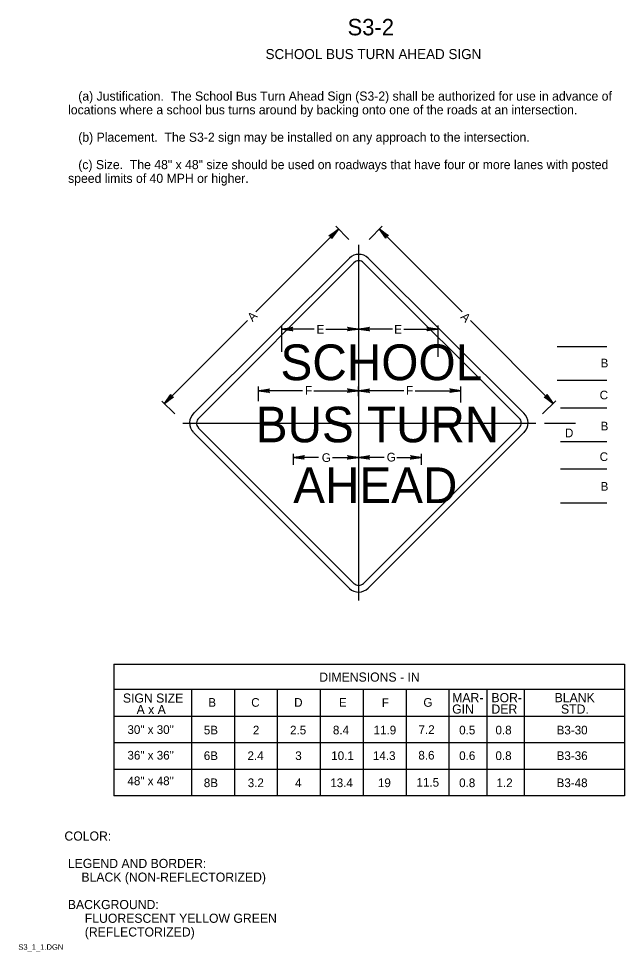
# Model space of a CAD drawing. Extents: x 0.013 to 0.178, y 0.004 to 0.259.
import ezdxf

# ---------------------------------------------------------------- set-up
doc = ezdxf.new("R2010")
doc.units = 0
for name, color, linetype in [('1', 7, 'Continuous'), ('2', 7, 'Continuous'), ('3', 7, 'Continuous')]:
    doc.layers.add(name, color=color, linetype=linetype)

# ---------------------------------------------------------------- blocks, each defined once
blk = doc.blocks.new('RARROW')
at = {"layer": '3'}
for p, q in [((-2.156, 0.28500000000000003), (-2.2665, 0.384625)), ((-2.2665, 0.384625), (0, 0)), ((0, 0), (-2.2665, -0.379125)), ((-2.156, 0.28500000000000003), (-2.075625, 0.12075)), ((0, 0), (-2.156, 0.28500000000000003)), ((-2.14975, -0.2705), (0, 0)), ((-2.075625, 0.12075), (0, 0)), ((0, 0), (-2.074, -0.108)), ((-2.2665, -0.379125), (-2.14975, -0.2705)), ((-2.074, -0.108), (-2.14975, -0.2705))]:
    blk.add_line(p, q, dxfattribs=at)

msp = doc.modelspace()

# ---------------------------------------------------------------- linework, layer by layer
at = {"layer": '1'}
for p, q in [((0.173625, 0.169375), (0.16, 0.169375)), ((0.173625, 0.160125), (0.16, 0.160125)), ((0.173625, 0.152625), (0.160875, 0.152625)), ((0.134125, 0.148375), (0.0575, 0.148375)), ((0.105625, 0.148375), (0.105625, 0.148375)), ((0.105625, 0.148375), (0.105625, 0.148375)), ((0.154125, 0.148375), (0.134125, 0.148375)), ((0.165, 0.148375), (0.1565, 0.148375)), ((0.173625, 0.143375), (0.160875, 0.143375)), ((0.173625, 0.135875), (0.160875, 0.135875)), ((0.173625, 0.12662500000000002), (0.160875, 0.12662500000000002))]:
    msp.add_line(p, q, dxfattribs=at)
at = {"layer": '3'}
for p, q in [((0.10300000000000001, 0.19875), (0.099375, 0.202375)), ((0.1085, 0.19875), (0.112125, 0.202375)), ((0.0775, 0.179), (0.100125, 0.201625)), ((0.134, 0.179), (0.111375, 0.201625)), ((0.105625, 0.19725), (0.105625, 0.1)), ((0.0605, 0.15125), (0.10312500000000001, 0.193625)), ((0.061875, 0.149875), (0.104375, 0.192375)), ((0.107, 0.192375), (0.149625, 0.149875)), ((0.10825, 0.193625), (0.150875, 0.15125)), ((0.07525, 0.176625), (0.0525, 0.153875)), ((0.13625, 0.176625), (0.15887500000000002, 0.153875)), ((0.084625, 0.168), (0.084625, 0.17525000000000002)), ((0.0935, 0.17425000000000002), (0.084625, 0.17425000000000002)), ((0.096625, 0.17425000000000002), (0.105625, 0.17425000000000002)), ((0.105625, 0.17550000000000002), (0.105625, 0.17525000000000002)), ((0.114875, 0.17425000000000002), (0.105625, 0.17425000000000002)), ((0.11800000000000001, 0.17425000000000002), (0.12737500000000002, 0.17425000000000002)), ((0.12737500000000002, 0.166625), (0.12737500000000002, 0.17525000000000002)), ((0.07825, 0.1545), (0.07825, 0.1585)), ((0.105625, 0.155875), (0.105625, 0.1585)), ((0.133625, 0.154125), (0.133625, 0.1585)), ((0.09025, 0.15737500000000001), (0.07825, 0.15737500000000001)), ((0.093375, 0.15737500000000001), (0.105625, 0.15737500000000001)), ((0.11800000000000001, 0.15737500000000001), (0.105625, 0.15737500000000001)), ((0.121125, 0.15737500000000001), (0.133625, 0.15737500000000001)), ((0.055375, 0.151), (0.051750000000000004, 0.1545)), ((0.156, 0.151), (0.15962500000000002, 0.154625)), ((0.10312500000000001, 0.10325000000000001), (0.0605, 0.145875)), ((0.104375, 0.104625), (0.06175, 0.14725)), ((0.149625, 0.14725), (0.107, 0.104625)), ((0.151, 0.146), (0.10825, 0.10337500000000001)), ((0.08778122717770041, 0.137125), (0.08778122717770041, 0.140125)), ((0.09469813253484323, 0.139125), (0.08778122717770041, 0.139125)), ((0.09845575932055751, 0.139125), (0.105625, 0.139125)), ((0.105625, 0.14025), (0.105625, 0.140125)), ((0.1126007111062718, 0.139125), (0.105625, 0.139125)), ((0.11608309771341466, 0.139125), (0.12286836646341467, 0.139125)), ((0.12286836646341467, 0.137125), (0.12286836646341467, 0.140125)), ((0.038625, 0.0825), (0.178375, 0.0825)), ((0.038625, 0.0825), (0.038625, 0.0465)), ((0.178375, 0.0825), (0.178375, 0.0465)), ((0.178375, 0.075625), (0.038625, 0.075625)), ((0.059875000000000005, 0.07575), (0.059875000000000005, 0.0465)), ((0.07162500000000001, 0.075625), (0.07162500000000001, 0.0465)), ((0.083375, 0.075625), (0.083375, 0.0465)), ((0.095125, 0.075625), (0.095125, 0.0465)), ((0.106875, 0.075625), (0.106875, 0.0465)), ((0.11862500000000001, 0.075625), (0.11862500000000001, 0.0465)), ((0.130375, 0.075625), (0.130375, 0.0465)), ((0.130375, 0.075625), (0.130375, 0.0465)), ((0.14075000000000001, 0.075625), (0.14075000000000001, 0.0465)), ((0.151, 0.075625), (0.151, 0.0465)), ((0.178375, 0.06825), (0.038625, 0.06825)), ((0.178375, 0.061), (0.038625, 0.061)), ((0.178375, 0.05375), (0.038625, 0.05375)), ((0.178375, 0.0465), (0.038625, 0.0465))]:
    msp.add_line(p, q, dxfattribs=at)
for centre, radius, start, end in [((0.10568750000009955, 0.19105909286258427), 0.003626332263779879, 45.03806666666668, 134.96193611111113), ((0.10569511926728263, 0.19107560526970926), 0.0018664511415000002, 45.03657222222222, 134.96044166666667), ((0.06311040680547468, 0.14857567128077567), 0.003732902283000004, 133.40603611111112, 225), ((0.14828904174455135, 0.14857109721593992), 0.0037233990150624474, 315.50790555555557, 46.011380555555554), ((0.06310643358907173, 0.148524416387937), 0.001827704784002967, 132.35789722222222, 223.9518611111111), ((0.14833975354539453, 0.14857807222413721), 0.0018258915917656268, 314.7557194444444, 45.25919444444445), ((0.1056239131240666, 0.10591956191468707), 0.003656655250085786, 226.8910611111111, 315.9033), ((0.1056874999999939, 0.10596032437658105), 0.0018723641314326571, 225.4938805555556, 314.5061194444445)]:
    msp.add_arc(centre, radius, start, end, dxfattribs=at)

# ---------------------------------------------------------------- block references
at = {"layer": '3', "xscale": 0.0013236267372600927}
for p, yscale, rotation in [((0.1, 0.2015), 0.0013093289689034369, 45.093773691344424), ((0.111375, 0.201625), 0.0013093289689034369, 134.9062263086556), ((0.084625, 0.17425000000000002), 0.001309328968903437, 180), ((0.105625, 0.17425000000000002), 0.001309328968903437, 180), ((0.0525, 0.153875), 0.0013093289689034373, -134.90622630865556), ((0.07825, 0.15737500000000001), 0.001309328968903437, 180), ((0.105625, 0.15737500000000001), 0.001309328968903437, 180), ((0.15887500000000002, 0.153875), 0.0013093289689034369, -45.093773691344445), ((0.08778122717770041, 0.139125), 0.001309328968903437, 180), ((0.105625, 0.139125), 0.001309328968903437, 180)]:
    msp.add_blockref('RARROW', p, dxfattribs=dict(at, yscale=yscale, rotation=rotation))
at = {"layer": '3', "xscale": 0.0013236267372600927, "yscale": 0.001309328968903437}
for p in [(0.105625, 0.17425000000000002), (0.12737500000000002, 0.17425000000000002), (0.105625, 0.15737500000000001), (0.133625, 0.15737500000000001), (0.105625, 0.139125), (0.12286836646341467, 0.139125)]:
    msp.add_blockref('RARROW', p, dxfattribs=at)

# ---------------------------------------------------------------- texts
at = {"layer": '1'}
for s, height, p in [('S3-2', 0.0045000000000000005, (0.10261806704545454, 0.254625)), ('SCHOOL BUS TURN AHEAD SIGN', 0.00275025, (0.08016680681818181, 0.248125)), ('COLOR:', 0.0024997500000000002, (0.025125, 0.034249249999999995)), (' LEGEND AND BORDER:', 0.0024997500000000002, (0.025125, 0.02674975)), ('     BLACK (NON-REFLECTORIZED)', 0.0024997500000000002, (0.025125, 0.023)), (' BACKGROUND:', 0.0024997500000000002, (0.025125, 0.015500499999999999)), ('      FLUORESCENT YELLOW GREEN', 0.0024997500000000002, (0.025125, 0.01175075)), ('      (REFLECTORIZED)', 0.0024997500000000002, (0.025125, 0.008001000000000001)), ('S3_1_1.DGN', 0.0015, (0.0125, 0.004375))]:
    msp.add_text(s, height=height, dxfattribs=at).set_placement(p)
at = {"layer": '2'}
for s, p in [('   (a) Justification.  The School Bus Turn Ahead Sign (S3-2) shall be authorized for use in advance of ', (0.026125, 0.23675025)), ('locations where a school bus turns around by backing onto one of the roads at an intersection.', (0.026125, 0.2330005)), ('   (b) Placement.  The S3-2 sign may be installed on any approach to the intersection.', (0.026125, 0.225501)), ('   (c) Size.  The 48" x 48" size should be used on roadways that have four or more lanes with posted', (0.026125, 0.2180015)), ('speed limits of 40 MPH or higher.', (0.026125, 0.21425175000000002))]:
    msp.add_text(s, height=0.0024997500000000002, dxfattribs=at).set_placement(p)
at = {"layer": '3'}
for rotation, p in [(45.093775, (0.076625, 0.176125)), (314.906225, (0.133375, 0.177375))]:
    msp.add_text('A', height=0.0023752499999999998, rotation=rotation, dxfattribs=at).set_placement(p)
for s, height, p in [('E', 0.0023752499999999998, (0.094125, 0.17300000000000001)), ('E', 0.0023752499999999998, (0.115375, 0.17300000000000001)), ('SCHOOL', 0.009777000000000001, (0.08425, 0.16025)), ('B', 0.0023752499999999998, (0.171875, 0.16375)), ('F', 0.0023752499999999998, (0.091, 0.15625)), ('F', 0.0023752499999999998, (0.11862500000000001, 0.15625)), ('C', 0.0023752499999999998, (0.171625, 0.155)), ('BUS TURN', 0.00975, (0.0775, 0.14325000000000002)), ('B', 0.0023752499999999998, (0.171875, 0.1465)), ('D', 0.0023752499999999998, (0.162125, 0.144625)), ('G', 0.0023752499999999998, (0.11333332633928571, 0.138)), ('C', 0.0023752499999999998, (0.171625, 0.138125)), ('G', 0.0023752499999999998, (0.09556364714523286, 0.137875)), ('AHEAD', 0.00975, (0.08774676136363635, 0.12662500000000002)), ('B', 0.0023752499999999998, (0.171875, 0.13)), ('DIMENSIONS - IN', 0.0024997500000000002, (0.09486310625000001, 0.07775)), ('SIGN SIZE', 0.0024997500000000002, (0.041125, 0.07200000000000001)), ('MAR-', 0.0024997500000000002, (0.13125, 0.072125)), ('BOR-', 0.0024997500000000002, (0.14200000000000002, 0.072125)), ('BLANK', 0.0024997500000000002, (0.15929515, 0.072125)), ('B', 0.0023752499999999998, (0.0645, 0.07087500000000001)), ('C', 0.0023752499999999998, (0.07625, 0.07087500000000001)), ('D', 0.0023752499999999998, (0.088, 0.07087500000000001)), ('E', 0.0023752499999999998, (0.10025, 0.07087500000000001)), ('F', 0.0023752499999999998, (0.112, 0.07084040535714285)), ('G', 0.0023752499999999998, (0.123375, 0.07087500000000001)), ('GIN', 0.0024997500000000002, (0.13125, 0.069)), ('DER', 0.0024997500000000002, (0.14200000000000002, 0.069)), ('STD.', 0.0024997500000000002, (0.16104515, 0.069)), ('A x A', 0.0024997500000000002, (0.044875, 0.068875)), ('30" x 30"', 0.0023752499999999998, (0.042370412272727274, 0.063437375)), ('5B', 0.0023752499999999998, (0.06326654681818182, 0.063312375)), ('2', 0.0023752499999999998, (0.07669853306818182, 0.063312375)), ('2.5', 0.0023752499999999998, (0.0868713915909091, 0.063312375)), ('8.4', 0.0023752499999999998, (0.09860699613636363, 0.063312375)), ('11.9', 0.0023752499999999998, (0.10974327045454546, 0.063312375)), ('7.2', 0.0023752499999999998, (0.12204497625, 0.063437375)), ('0.5', 0.0023752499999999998, (0.13317187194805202, 0.063312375)), ('0.8', 0.0023752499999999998, (0.1431055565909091, 0.063312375)), ('B3-30', 0.0023752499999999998, (0.15984026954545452, 0.063312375)), ('36" x 36"', 0.0023752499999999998, (0.042370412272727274, 0.05642473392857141)), ('6B', 0.0023752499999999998, (0.06326654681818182, 0.05629973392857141)), ('2.4', 0.0023752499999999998, (0.07523199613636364, 0.05629973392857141)), ('3', 0.0023752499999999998, (0.08830661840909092, 0.05629973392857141)), ('10.1', 0.0023752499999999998, (0.09814562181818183, 0.05629973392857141)), ('14.3', 0.0023752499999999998, (0.10955828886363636, 0.05629973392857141)), ('8.6', 0.0023752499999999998, (0.1219935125, 0.05642473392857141)), ('0.6', 0.0023752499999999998, (0.13316899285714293, 0.05629973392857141)), ('0.8', 0.0023752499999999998, (0.1431055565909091, 0.05629973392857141)), ('B3-36', 0.0023752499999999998, (0.15984530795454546, 0.05629973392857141)), ('48" x 48"', 0.0023752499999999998, (0.042370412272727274, 0.04941209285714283)), ('8B', 0.0023752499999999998, (0.06326654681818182, 0.04888021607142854)), ('3.2', 0.0023752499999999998, (0.07529497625, 0.04888021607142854)), ('4', 0.0023752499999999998, (0.08826055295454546, 0.04888021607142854)), ('13.4', 0.0023752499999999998, (0.09788722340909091, 0.04888021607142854)), ('19', 0.0023752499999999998, (0.11093089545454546, 0.04888021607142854)), ('11.5', 0.0023752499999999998, (0.12149255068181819, 0.04900521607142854)), ('0.8', 0.0023752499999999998, (0.133156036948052, 0.04888021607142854)), ('1.2', 0.0023752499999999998, (0.1433859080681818, 0.04888021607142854)), ('B3-48', 0.0023752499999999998, (0.15983235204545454, 0.04888021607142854))]:
    msp.add_text(s, height=height, dxfattribs=at).set_placement(p)

doc.saveas('drawing.dxf')
